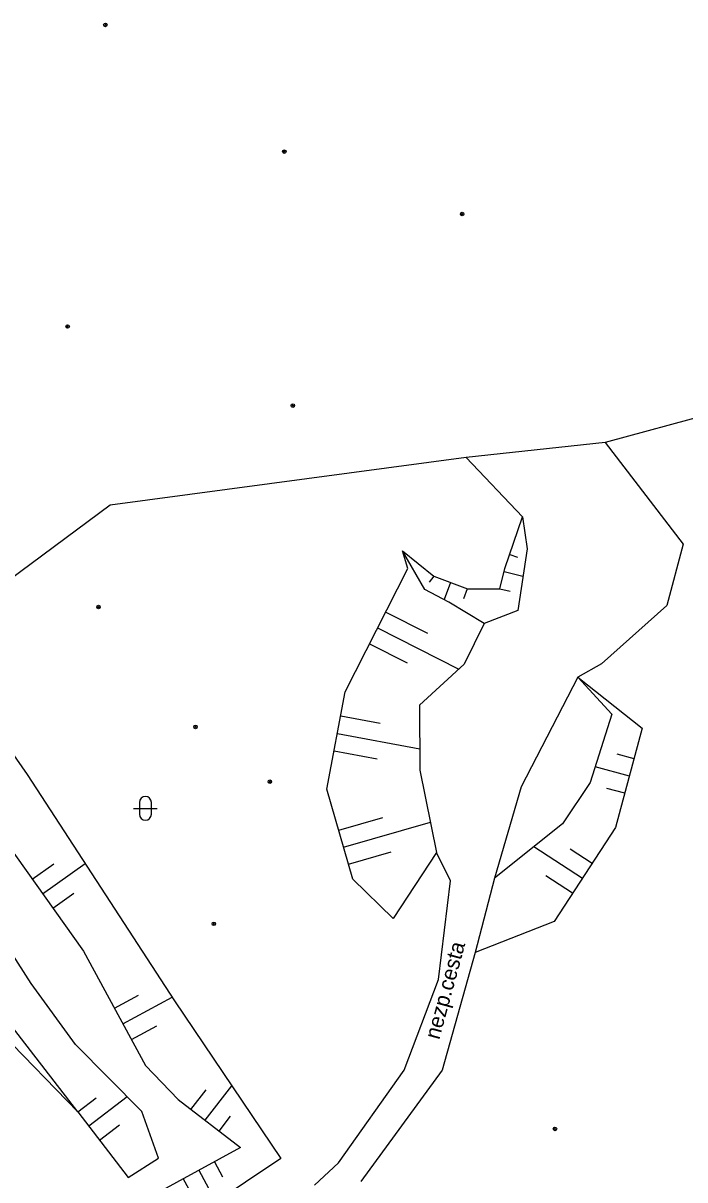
# Model space of a CAD drawing. Extents: x -639440 to -639026, y -1138850 to -1138262.
# Drawn here: x -639242.78 to -639214.88, y -1138562.45 to -1138513.71 of the extents above; entities that cross this region are included whole.
import ezdxf

# ---------------------------------------------------------------- set-up
doc = ezdxf.new("R2010")
doc.units = 0
for name, color, linetype in [('Vrstva 10', 7, 'Continuous'), ('Vrstva 11', 7, 'Continuous'), ('Vrstva 14', 7, 'Continuous'), ('Vrstva 15', 7, 'Continuous'), ('Vrstva 20', 7, 'Continuous'), ('Vrstva 36', 7, 'Continuous'), ('Vrstva 40', 7, 'Continuous')]:
    doc.layers.add(name, color=color, linetype=linetype)

msp = doc.modelspace()

# ---------------------------------------------------------------- linework, layer by layer
at = {"layer": 'Vrstva 10'}
for p, q in [((-639211.43, -1138529.52), (-639218.24, -1138531.37)), ((-639218.24, -1138531.37), (-639224.1, -1138532.01)), ((-639224.1, -1138532.01), (-639239.11, -1138534.01)), ((-639239.11, -1138534.01), (-639244.97, -1138538.36))]:
    msp.add_line(p, q, dxfattribs=at)
at = {"layer": 'Vrstva 11'}
for p, q in [((-639218.24, -1138531.37), (-639214.96, -1138535.66)), ((-639221.73, -1138534.51), (-639224.1, -1138532.01)), ((-639214.96, -1138535.66), (-639215.65, -1138538.25)), ((-639215.65, -1138538.25), (-639218.4, -1138540.7)), ((-639218.4, -1138540.7), (-639219.4, -1138541.26)), ((-639219.4, -1138541.26), (-639221.79, -1138545.89)), ((-639221.79, -1138545.89), (-639222.91, -1138549.74)), ((-639224.76, -1138549.85), (-639225.35, -1138548.65)), ((-639225.27, -1138554.01), (-639224.76, -1138549.85)), ((-639222.91, -1138549.74), (-639223.73, -1138552.86)), ((-639223.73, -1138552.86), (-639225.11, -1138557.83)), ((-639226.72, -1138557.82), (-639225.27, -1138554.01)), ((-639229.48, -1138561.73), (-639226.72, -1138557.82)), ((-639225.11, -1138557.83), (-639228.54, -1138562.51)), ((-639230.49, -1138562.67), (-639229.48, -1138561.73))]:
    msp.add_line(p, q, dxfattribs=at)
at = {"layer": 'Vrstva 14'}
for p, q in [((-639222.47, -1138536.69), (-639221.73, -1138534.51)), ((-639221.73, -1138534.51), (-639221.53, -1138535.85)), ((-639226.56, -1138536.68), (-639226.79, -1138535.94)), ((-639225.84, -1138537.57), (-639226.79, -1138535.94)), ((-639226.79, -1138535.94), (-639225.46, -1138537.01)), ((-639221.53, -1138535.85), (-639221.93, -1138538.45)), ((-639229.2, -1138541.88), (-639226.56, -1138536.68)), ((-639225.46, -1138537.01), (-639224.05, -1138537.54)), ((-639222.68, -1138537.54), (-639222.47, -1138536.69)), ((-639224.05, -1138537.54), (-639222.68, -1138537.54)), ((-639224.83, -1138538.1), (-639225.84, -1138537.57)), ((-639223.35, -1138539), (-639224.83, -1138538.1)), ((-639221.93, -1138538.45), (-639223.35, -1138539)), ((-639223.35, -1138539), (-639224.18, -1138540.71)), ((-639246.79, -1138539.42), (-639242.6, -1138545.37)), ((-639224.18, -1138540.71), (-639226.07, -1138542.44)), ((-639219.4, -1138541.26), (-639216.68, -1138543.42)), ((-639219.4, -1138541.26), (-639217.96, -1138542.82)), ((-639229.97, -1138545.99), (-639229.2, -1138541.88)), ((-639226.07, -1138542.44), (-639226.05, -1138545.18)), ((-639217.96, -1138542.82), (-639218.88, -1138545.7)), ((-639216.68, -1138543.42), (-639217.81, -1138547.6)), ((-639226.05, -1138545.18), (-639225.35, -1138548.65)), ((-639242.6, -1138545.37), (-639236.4, -1138554.9)), ((-639218.88, -1138545.7), (-639220.04, -1138547.45)), ((-639228.88, -1138549.78), (-639229.97, -1138545.99)), ((-639244.72, -1138546.51), (-639240.23, -1138552.81)), ((-639220.04, -1138547.45), (-639222.91, -1138549.74)), ((-639217.81, -1138547.6), (-639220.39, -1138551.56)), ((-639225.35, -1138548.65), (-639227.18, -1138551.43)), ((-639242.44, -1138554.18), (-639245.76, -1138548.98)), ((-639227.18, -1138551.43), (-639228.88, -1138549.78)), ((-639240.47, -1138559.58), (-639247.03, -1138551.15)), ((-639220.39, -1138551.56), (-639223.73, -1138552.86)), ((-639240.23, -1138552.81), (-639237.62, -1138557.63)), ((-639240.57, -1138556.74), (-639242.44, -1138554.18)), ((-639236.4, -1138554.9), (-639231.92, -1138561.55)), ((-639243.69, -1138556.27), (-639240.47, -1138559.58)), ((-639237.77, -1138559.57), (-639240.57, -1138556.74)), ((-639237.62, -1138557.63), (-639236.24, -1138559.06)), ((-639236.24, -1138559.06), (-639233.62, -1138561.09)), ((-639240.47, -1138559.58), (-639238.35, -1138562.35)), ((-639237.07, -1138561.54), (-639237.77, -1138559.57)), ((-639233.62, -1138561.09), (-639238.53, -1138563.76)), ((-639238.35, -1138562.35), (-639237.07, -1138561.54)), ((-639231.92, -1138561.55), (-639237.32, -1138565.16))]:
    msp.add_line(p, q, dxfattribs=at)
at = {"layer": 'Vrstva 15'}
for p, q in [((-639222.269, -1138536.098), (-639221.936, -1138536.211)), ((-639225.46, -1138537.01), (-639225.665, -1138537.265)), ((-639222.5, -1138536.811), (-639221.708, -1138537.007)), ((-639224.758, -1138537.274), (-639225.029, -1138537.995)), ((-639224.056, -1138537.538), (-639224.214, -1138537.958)), ((-639222.68, -1138537.539), (-639222.251, -1138537.645)), ((-639227.495, -1138538.522), (-639225.738, -1138539.414)), ((-639227.835, -1138539.191), (-639224.416, -1138540.926)), ((-639228.174, -1138539.859), (-639226.591, -1138540.663)), ((-639229.39, -1138542.897), (-639227.726, -1138543.209)), ((-639229.529, -1138543.634), (-639226.057, -1138544.284)), ((-639229.667, -1138544.371), (-639227.859, -1138544.71)), ((-639217.028, -1138544.707), (-639217.734, -1138544.516)), ((-639217.224, -1138545.431), (-639218.669, -1138545.04)), ((-639217.419, -1138546.155), (-639218.167, -1138545.953)), ((-639229.476, -1138547.708), (-639227.616, -1138547.173)), ((-639229.269, -1138548.429), (-639225.607, -1138547.376)), ((-639229.061, -1138549.15), (-639227.26, -1138548.631)), ((-639219.206, -1138549.742), (-639221.247, -1138548.413)), ((-639218.796, -1138549.114), (-639219.713, -1138548.517)), ((-639242.39, -1138549.78), (-639241.482, -1138549.132)), ((-639241.954, -1138550.39), (-639240.164, -1138549.114)), ((-639219.615, -1138550.371), (-639220.74, -1138549.638)), ((-639241.519, -1138551.001), (-639240.637, -1138550.372)), ((-639238.928, -1138555.215), (-639237.917, -1138554.668)), ((-639238.571, -1138555.874), (-639236.497, -1138554.751)), ((-639238.214, -1138556.534), (-639237.146, -1138555.956)), ((-639235.11, -1138559.935), (-639233.986, -1138558.484)), ((-639240.47, -1138559.581), (-639239.698, -1138558.99)), ((-639240.014, -1138560.176), (-639238.396, -1138558.938)), ((-639235.703, -1138559.476), (-639235.065, -1138558.652)), ((-639234.517, -1138560.395), (-639234.031, -1138559.767)), ((-639239.558, -1138560.772), (-639238.711, -1138560.123)), ((-639234.715, -1138561.686), (-639234.37, -1138562.321)), ((-639236.033, -1138562.402), (-639235.655, -1138563.098)), ((-639235.374, -1138562.044), (-639234.65, -1138563.375))]:
    msp.add_line(p, q, dxfattribs=at)
at = {"layer": 'Vrstva 20'}
for centre, radius in [((-639239.31, -1138513.78), 0.075), ((-639239.31, -1138513.78), 0.0204), ((-639231.77, -1138519.12), 0.075), ((-639231.77, -1138519.12), 0.0204), ((-639224.27, -1138521.75), 0.075), ((-639224.27, -1138521.75), 0.0204), ((-639240.9, -1138526.49), 0.075), ((-639240.9, -1138526.49), 0.0204), ((-639231.41, -1138529.82), 0.075), ((-639231.41, -1138529.82), 0.0204), ((-639239.6, -1138538.31), 0.075), ((-639239.6, -1138538.31), 0.0204), ((-639235.51, -1138543.36), 0.075), ((-639235.51, -1138543.36), 0.0204), ((-639232.38, -1138545.67), 0.075), ((-639232.38, -1138545.67), 0.0204), ((-639234.74, -1138551.66), 0.075), ((-639234.74, -1138551.66), 0.0204), ((-639220.36, -1138560.3), 0.075), ((-639220.36, -1138560.3), 0.0204)]:
    msp.add_circle(centre, radius, dxfattribs=at)
at = {"layer": 'Vrstva 36'}
for p, q in [((-639238.123, -1138546.793), (-639237.123, -1138546.793)), ((-639237.873, -1138546.543), (-639237.873, -1138547.043)), ((-639237.373, -1138546.543), (-639237.373, -1138547.043))]:
    msp.add_line(p, q, dxfattribs=at)
for centre, start, end in [((-639237.622, -1138546.543), 0, 180), ((-639237.622, -1138547.043), 180, 0)]:
    msp.add_arc(centre, 0.25, start, end, dxfattribs=at)

# ---------------------------------------------------------------- texts
at = {"layer": 'Vrstva 40'}
msp.add_text('nezp.cesta', height=0.65, rotation=74.7868, dxfattribs=at).set_placement((-639225.24, -1138556.567))

doc.saveas('drawing.dxf')
